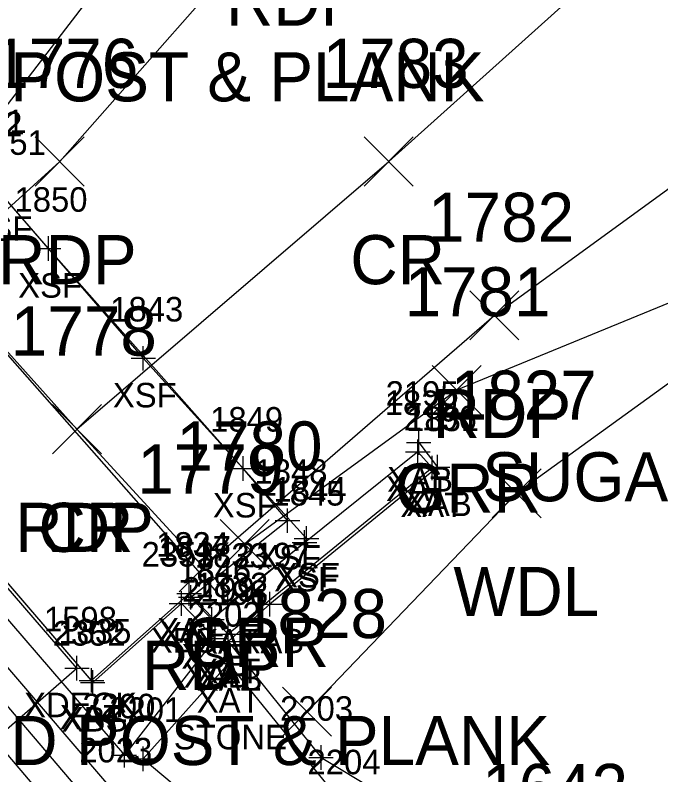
# Model space of a CAD drawing. Extents: x 1647133 to 1649138, y 411736 to 414924.
# Drawn here: x 1648982.81 to 1649009.12, y 412208.47 to 412239.42 of the extents above; entities that cross this region are included whole.
import ezdxf

# ---------------------------------------------------------------- set-up
doc = ezdxf.new("R2010")
doc.units = 0
for name, color, linetype in [('B_A', 7, 'Continuous'), ('B_C', 7, 'Continuous'), ('B_I', 7, 'Continuous'), ('B_TIC', 7, 'Continuous'), ('BDEFAULT', 7, 'Continuous'), ('BELB', 7, 'Continuous'), ('BFT', 7, 'Continuous'), ('BSE', 7, 'Continuous'), ('BSUBM', 7, 'Continuous'), ('L_A', 7, 'Continuous'), ('L_I', 7, 'Continuous'), ('L_TIC', 7, 'Continuous'), ('LAWA', 7, 'Continuous'), ('P_A', 7, 'Continuous'), ('P_I', 7, 'Continuous'), ('P_TIC', 7, 'Continuous'), ('PET', 7, 'Continuous'), ('PRC', 7, 'Continuous'), ('R_A', 7, 'Continuous'), ('R_C', 7, 'Continuous'), ('R_I', 7, 'Continuous'), ('R_TIC', 7, 'Continuous'), ('RGR', 7, 'Continuous'), ('S_C', 7, 'Continuous')]:
    doc.layers.add(name, color=color, linetype=linetype)

msp = doc.modelspace()

# ---------------------------------------------------------------- linework, layer by layer
at = {"layer": 'B_TIC'}
for p, q in [((1648984.177, 412229.914), (1648984.253, 412229.914)), ((1648988.035, 412225.443), (1648988.111, 412225.443)), ((1648999.255, 412222.01), (1648999.331, 412222.01)), ((1648999.222, 412221.632), (1648999.298, 412221.632)), ((1648999.222, 412221.632), (1648999.298, 412221.632)), ((1648992.108, 412220.957), (1648992.183, 412220.957)), ((1648999.805, 412220.975), (1648999.881, 412220.975)), ((1649000.021, 412221.012), (1649000.096, 412221.012)), ((1648993.913, 412218.83), (1648993.988, 412218.83)), ((1648994.685, 412218.108), (1648994.761, 412218.108)), ((1648994.603, 412217.943), (1648994.678, 412217.943)), ((1648989.901, 412215.859), (1648989.977, 412215.859)), ((1648989.973, 412215.704), (1648990.048, 412215.704)), ((1648989.595, 412215.456), (1648989.671, 412215.456)), ((1648991.483, 412215.41), (1648991.559, 412215.41)), ((1648993.195, 412215.427), (1648993.27, 412215.427)), ((1648990.83, 412214.803), (1648990.906, 412214.803)), ((1648990.964, 412214.026), (1648991.04, 412214.026)), ((1648991.496, 412214.206), (1648991.572, 412214.206)), ((1648991.495, 412213.898), (1648991.571, 412213.898)), ((1648985.334, 412212.818), (1648985.409, 412212.818)), ((1648991.509, 412213.009), (1648991.585, 412213.009)), ((1648985.92, 412212.32), (1648985.996, 412212.32)), ((1648985.975, 412212.236), (1648986.05, 412212.236)), ((1648987.264, 412209.275), (1648987.34, 412209.275)), ((1648987.264, 412209.275), (1648987.34, 412209.275)), ((1648988.033, 412209.126), (1648988.109, 412209.126)), ((1648988.033, 412209.126), (1648988.109, 412209.126)), ((1648995.277, 412209.174), (1648995.353, 412209.174))]:
    msp.add_line(p, q, dxfattribs=at)
for points in [[(1648984.174, 412229.414), (1648984.174, 412230.414)], [(1648983.674, 412229.914), (1648984.674, 412229.914)], [(1648988.032, 412224.943), (1648988.032, 412225.943)], [(1648987.532, 412225.443), (1648988.532, 412225.443)], [(1648999.252, 412221.51), (1648999.252, 412222.51)], [(1648999.219, 412221.132), (1648999.219, 412222.132)], [(1648999.219, 412221.132), (1648999.219, 412222.132)], [(1648998.752, 412222.01), (1648999.752, 412222.01)], [(1648992.104, 412220.457), (1648992.104, 412221.457)], [(1648998.719, 412221.632), (1648999.719, 412221.632)], [(1648998.719, 412221.632), (1648999.719, 412221.632)], [(1648999.802, 412220.475), (1648999.802, 412221.475)], [(1649000.017, 412220.512), (1649000.017, 412221.512)], [(1648991.604, 412220.957), (1648992.604, 412220.957)], [(1648999.302, 412220.975), (1649000.302, 412220.975)], [(1648999.517, 412221.012), (1649000.517, 412221.012)], [(1648993.909, 412218.33), (1648993.909, 412219.33)], [(1648993.409, 412218.83), (1648994.409, 412218.83)], [(1648994.599, 412217.443), (1648994.599, 412218.443)], [(1648994.682, 412217.608), (1648994.682, 412218.608)], [(1648994.182, 412218.108), (1648995.182, 412218.108)], [(1648994.099, 412217.943), (1648995.099, 412217.943)], [(1648989.898, 412215.359), (1648989.898, 412216.359)], [(1648989.969, 412215.204), (1648989.969, 412216.204)], [(1648989.398, 412215.859), (1648990.398, 412215.859)], [(1648989.592, 412214.956), (1648989.592, 412215.956)], [(1648991.48, 412214.91), (1648991.48, 412215.91)], [(1648993.191, 412214.927), (1648993.191, 412215.927)], [(1648989.469, 412215.704), (1648990.469, 412215.704)], [(1648989.092, 412215.456), (1648990.092, 412215.456)], [(1648990.827, 412214.303), (1648990.827, 412215.303)], [(1648990.98, 412215.41), (1648991.98, 412215.41)], [(1648992.691, 412215.427), (1648993.691, 412215.427)], [(1648990.327, 412214.803), (1648991.327, 412214.803)], [(1648991.493, 412213.706), (1648991.493, 412214.706)], [(1648990.961, 412213.526), (1648990.961, 412214.526)], [(1648991.492, 412213.398), (1648991.492, 412214.398)], [(1648990.461, 412214.026), (1648991.461, 412214.026)], [(1648990.993, 412214.206), (1648991.993, 412214.206)], [(1648990.992, 412213.898), (1648991.992, 412213.898)], [(1648991.506, 412212.509), (1648991.506, 412213.509)], [(1648985.33, 412212.318), (1648985.33, 412213.318)], [(1648984.83, 412212.818), (1648985.83, 412212.818)], [(1648985.917, 412211.82), (1648985.917, 412212.82)], [(1648991.006, 412213.009), (1648992.006, 412213.009)], [(1648985.971, 412211.736), (1648985.971, 412212.736)], [(1648985.417, 412212.32), (1648986.417, 412212.32)], [(1648985.471, 412212.236), (1648986.471, 412212.236)], [(1648987.261, 412208.775), (1648987.261, 412209.775)], [(1648987.261, 412208.775), (1648987.261, 412209.775)], [(1648995.274, 412208.674), (1648995.274, 412209.674)], [(1648988.03, 412208.626), (1648988.03, 412209.626)], [(1648988.03, 412208.626), (1648988.03, 412209.626)], [(1648986.761, 412209.275), (1648987.761, 412209.275)], [(1648986.761, 412209.275), (1648987.761, 412209.275)], [(1648987.53, 412209.126), (1648988.53, 412209.126)], [(1648987.53, 412209.126), (1648988.53, 412209.126)], [(1648994.774, 412209.174), (1648995.774, 412209.174)]]:
    msp.add_lwpolyline(points, dxfattribs=at)
at = {"layer": 'BDEFAULT'}
msp.add_lwpolyline([(1648977.204, 412229.977), (1648981.283, 412233.076), (1648981.479, 412232.993), (1648988.032, 412225.443), (1648994.682, 412218.108), (1648994.599, 412217.943), (1648990.827, 412214.803), (1648989.969, 412215.704), (1648993.909, 412218.83), (1648992.104, 412220.957), (1648984.174, 412229.914), (1648982.148, 412232.234), (1648978.38, 412228.778)], dxfattribs=at)
at = {"layer": 'BELB'}
msp.add_lwpolyline([(1648856.366, 412097.638), (1648904.081, 412141.155), (1648932.964, 412166.557), (1648970.055, 412199.522), (1648985.33, 412212.818), (1648974.892, 412224.907)], dxfattribs=at)
at = {"layer": 'BFT'}
for points in [[(1648969.053, 412251.503), (1648967.008, 412251.583), (1648967.16, 412237.956), (1648967.307, 412234.686), (1648967.339, 412227.16), (1648986.205, 412204.915), (1649003.564, 412196.539), (1649004.665, 412197.942)], [(1648969.525, 412251.264), (1648968.489, 412251.237), (1648968.622, 412227.573), (1648987.025, 412205.95), (1649003.857, 412197.685), (1649004.163, 412198.216)]]:
    msp.add_lwpolyline(points, dxfattribs=at)
at = {"layer": 'BSE'}
for points in [[(1648976.861, 412229.959), (1648978.236, 412228.62), (1648974.623, 412225.452), (1648985.971, 412212.236), (1648989.592, 412215.456)], [(1648972.016, 412226.979), (1648987.261, 412209.275)], [(1648989.592, 412215.456), (1648990.961, 412214.026)]]:
    msp.add_lwpolyline(points, dxfattribs=at)
at = {"layer": 'BSUBM'}
for points in [[(1648980.212, 412272.224), (1648969.681, 412271.317), (1648969.261, 412266.421), (1648968.934, 412254.381), (1648969.053, 412251.503), (1648969.525, 412251.264), (1648969.788, 412227.697), (1648987.092, 412207.478), (1648990.118, 412205.514), (1649004.163, 412198.216), (1649004.665, 412197.942), (1649016.348, 412193.098), (1649025.312, 412183.014), (1649046.031, 412166.296)], [(1648999.219, 412221.632), (1648999.802, 412220.975), (1648991.493, 412214.206), (1648989.898, 412215.859), (1648985.917, 412212.32), (1648974.64, 412225.453), (1648978.473, 412228.815), (1648976.701, 412230.631), (1648977.464, 412231.306)], [(1648999.219, 412221.632), (1648991.48, 412215.41), (1648977.464, 412231.306)], [(1648999.252, 412222.01), (1649000.017, 412221.012), (1648993.191, 412215.427), (1648991.492, 412213.898), (1648995.274, 412209.174), (1649004.473, 412203.654), (1649010.456, 412199.768)], [(1648990.961, 412214.026), (1648987.261, 412209.275)], [(1648988.03, 412209.126), (1648991.506, 412213.009), (1648996.391, 412206.994), (1649003.26, 412202.795), (1649010.456, 412199.768), (1649020.036, 412194.102), (1649031.356, 412182.024), (1649047.922, 412168.893)], [(1648988.03, 412209.126), (1648994.262, 412203.891), (1649001.042, 412200.278), (1649007.864, 412197.371), (1649018.249, 412192.591), (1649029.488, 412180.719), (1649045.657, 412167.83), (1649047.922, 412168.893)]]:
    msp.add_lwpolyline(points, dxfattribs=at)
at = {"layer": 'L_TIC'}
for points in [[(1649002.248, 412218.943), (1649004.248, 412220.943)], [(1649004.248, 412218.943), (1649002.248, 412220.943)], [(1648993.704, 412210.046), (1648995.704, 412212.046)], [(1648995.704, 412210.046), (1648993.704, 412212.046)]]:
    msp.add_lwpolyline(points, dxfattribs=at)
at = {"layer": 'LAWA'}
msp.add_lwpolyline([(1649111.119, 412178.299), (1649089.042, 412199.035), (1649075.25, 412213.993), (1649058.93, 412228.309), (1649052.095, 412230.86), (1649036.041, 412232.414), (1649032.165, 412233.292), (1649023.706, 412232.35), (1649011.835, 412226.16), (1649003.248, 412219.943), (1648994.704, 412211.046)], dxfattribs=at)
at = {"layer": 'P_TIC'}
for points in [[(1648983.626, 412232.464), (1648985.626, 412234.464)], [(1648985.626, 412232.464), (1648983.626, 412234.464)], [(1648997.031, 412232.463), (1648999.031, 412234.463)], [(1648999.031, 412232.463), (1648997.031, 412234.463)], [(1649001.33, 412226.191), (1649003.33, 412228.191)], [(1649003.33, 412226.191), (1649001.33, 412228.191)], [(1648984.327, 412221.555), (1648986.327, 412223.555)], [(1648986.327, 412221.555), (1648984.327, 412223.555)], [(1648984.327, 412221.555), (1648986.327, 412223.555)], [(1648986.327, 412221.555), (1648984.327, 412223.555)], [(1648989.487, 412215.934), (1648991.487, 412217.934)], [(1648991.487, 412215.934), (1648989.487, 412217.934)]]:
    msp.add_lwpolyline(points, dxfattribs=at)
at = {"layer": 'PET'}
msp.add_lwpolyline([(1648998.767, 412333.423), (1648994.313, 412324.566), (1648993.834, 412315.066), (1649000.687, 412300.559), (1649003.42, 412288.198), (1649004.904, 412270.19), (1649001.609, 412254.477), (1648993.905, 412243.995), (1648984.626, 412233.464), (1648979.622, 412228.916), (1648985.327, 412222.555), (1648990.487, 412216.934), (1649002.33, 412227.191), (1649016.429, 412237.436), (1649036.674, 412252.918), (1649058.783, 412267.778), (1649074.295, 412277.904), (1649090.06, 412287.47)], dxfattribs=at)
at = {"layer": 'PRC'}
msp.add_lwpolyline([(1648985.327, 412222.555), (1648998.031, 412233.463), (1649011.263, 412245.342), (1649030.664, 412261.202), (1649052.944, 412275.662), (1649084.878, 412295.987)], dxfattribs=at)
at = {"layer": 'R_TIC'}
for points in [[(1648999.802, 412223.157), (1649001.802, 412225.157)], [(1649001.802, 412223.157), (1648999.802, 412225.157)], [(1648991.163, 412216.871), (1648993.163, 412218.871)], [(1648993.163, 412216.871), (1648991.163, 412218.871)]]:
    msp.add_lwpolyline(points, dxfattribs=at)
at = {"layer": 'RGR'}
for points in [[(1648989.49, 412244.914), (1648979.455, 412231.845)], [(1648992.163, 412217.871), (1649000.802, 412224.157), (1649028.445, 412235.497)]]:
    msp.add_lwpolyline(points, dxfattribs=at)

# ---------------------------------------------------------------- texts
at = {"layer": 'B_A'}
for s, p in [('XSF', (1648980.908, 412230.234)), ('XSF', (1648982.933, 412227.914)), ('XSF', (1648986.792, 412223.443)), ('XAB', (1648997.972, 412220.01)), ('XAT', (1648997.924, 412219.632)), ('XAT', (1648997.924, 412219.632)), ('XSF', (1648990.864, 412218.957)), ('XAT', (1648998.506, 412218.975)), ('XAB', (1648998.738, 412219.012)), ('XSF', (1648992.669, 412216.83)), ('XSF', (1648993.442, 412216.108)), ('XSF', (1648993.359, 412215.943)), ('XAT', (1648988.602, 412213.859)), ('XSF', (1648988.729, 412213.704)), ('XBS', (1648988.332, 412213.456)), ('XAT', (1648990.184, 412213.41)), ('XAB', (1648991.912, 412213.427)), ('XSF', (1648989.587, 412212.803)), ('XAT', (1648990.197, 412212.206)), ('XAB', (1648989.681, 412212.026)), ('XAB', (1648990.212, 412211.898)), ('XDECK', (1648983.173, 412210.818)), ('XAT', (1648990.211, 412211.009)), ('XAT', (1648984.622, 412210.32)), ('XBS', (1648984.711, 412210.236))]:
    msp.add_text(s, height=1, dxfattribs=at).set_placement(p)
at = {"layer": 'B_C'}
msp.add_text('STONE', height=1, dxfattribs=at).set_placement((1648989.278, 412209.509))
at = {"layer": 'B_I'}
for s, p in [('1842', (1648980.132, 412234.493)), ('1841', (1648980.22, 412234.576)), ('1851', (1648981.085, 412233.734)), ('1850', (1648982.784, 412231.414)), ('1843', (1648986.685, 412226.943)), ('2195', (1648997.905, 412223.51)), ('1829', (1648997.868, 412223.132)), ('1829', (1648997.868, 412223.132)), ('1849', (1648990.754, 412222.457)), ('2196', (1648998.643, 412222.512)), ('1831', (1648998.739, 412222.475)), ('1848', (1648992.563, 412220.33)), ('1844', (1648993.335, 412219.608)), ('1845', (1648993.253, 412219.443)), ('1834', (1648988.551, 412217.359)), ('1847', (1648988.623, 412217.204)), ('2353', (1648987.962, 412216.956)), ('1833', (1648990.133, 412216.91)), ('2197', (1648991.845, 412216.927)), ('1846', (1648989.453, 412216.303)), ('2199', (1648989.61, 412215.526)), ('1832', (1648990.146, 412215.706)), ('2198', (1648990.145, 412215.398)), ('1598', (1648983.984, 412214.318)), ('2202', (1648989.837, 412214.509)), ('2352', (1648984.341, 412213.736)), ('1835', (1648984.57, 412213.82)), ('2200', (1648985.548, 412210.775)), ('2200', (1648985.548, 412210.775)), ('2201', (1648986.644, 412210.626)), ('2201', (1648986.644, 412210.626)), ('2203', (1648993.604, 412210.674)), ('2023', (1648985.422, 412208.978)), ('2204', (1648994.722, 412208.494))]:
    msp.add_text(s, height=1, dxfattribs=at).set_placement(p)
at = {"layer": 'L_A'}
msp.add_text('WDL', height=2, dxfattribs=at).set_placement((1649000.666, 412214.943))
at = {"layer": 'L_I'}
for s, p in [('1827', (1649000.556, 412222.943)), ('1828', (1648992.011, 412214.046)), ('1642', (1649001.831, 412206.917))]:
    msp.add_text(s, height=2, dxfattribs=at).set_placement(p)
at = {"layer": 'P_A'}
for s, p in [('RDP', (1648991.393, 412238.995)), ('RDP', (1648982.114, 412228.464)), ('CR', (1648996.465, 412228.463)), ('RDP', (1648999.818, 412222.191)), ('CR', (1648983.76, 412217.555)), ('RDP', (1648982.815, 412217.555)), ('RDP', (1648987.976, 412211.934))]:
    msp.add_text(s, height=2, dxfattribs=at).set_placement(p)
at = {"layer": 'P_I'}
for s, p in [('1776', (1648981.878, 412236.464)), ('1783', (1648995.339, 412236.463)), ('1782', (1648999.637, 412230.191)), ('1778', (1648982.634, 412225.555)), ('1778', (1648982.634, 412225.555)), ('1779', (1648987.787, 412219.934))]:
    msp.add_text(s, height=2, dxfattribs=at).set_placement(p)
at = {"layer": 'R_A'}
for p in [(1648998.29, 412219.157), (1648989.651, 412212.871)]:
    msp.add_text('GRR', height=2, dxfattribs=at).set_placement(p)
at = {"layer": 'R_C'}
for p in [(1648973.254, 412235.914), (1648975.926, 412208.871)]:
    msp.add_text('WOOD POST & PLANK', height=2, dxfattribs=at).set_placement(p)
at = {"layer": 'R_I'}
for s, p in [('1781', (1648998.676, 412227.157)), ('1780', (1648989.383, 412220.871))]:
    msp.add_text(s, height=2, dxfattribs=at).set_placement(p)
at = {"layer": 'S_C'}
msp.add_text('SUGARBUSH FARM', height=2, dxfattribs=at).set_placement((1649001.84, 412219.617))

doc.saveas('drawing.dxf')
